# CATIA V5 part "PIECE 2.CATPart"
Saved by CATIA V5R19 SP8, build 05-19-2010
Part number: PIECE 2
Bounding box of the stored display mesh (mm): x -6 to 0, y -17.5 to 17.5, z -1 to 19
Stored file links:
  C:\Users\ThinkMotion\Desktop\EU_thinkMotion\iao\IAO_MMS_Groupe3\jbuffard\jbuffard\PIECE 2.CATPart
  C:\Users\ThinkMotion\Desktop\EU_thinkMotion\iao\IAO_MMS_Groupe3\jbuffard\jbuffard\Mecanisme a coulisse a quatre elements de la griffe d'une camera.CATProduct
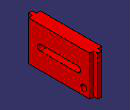
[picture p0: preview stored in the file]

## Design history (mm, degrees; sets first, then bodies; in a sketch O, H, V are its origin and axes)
External parameters (linked from other documents)
  `External.Diametre doigt/rainures` = 0.0015
  External.Largeur = 0.031
  `External.Demi-largeur` = 0.0155
Set1
  Plane1: linked copy from another document
  Plane2: linked copy from another document
  Point1 to Point3: linked copy from another document
  Plane3: linked copy from another document
Body1 (main body)
  Sketch1 on Plane1, origin (0, 0, 19), H (1, 0, 0), V (0, 1, 0)
    line L1 (-4, 17.5) -> (-2, 17.5)
    line L2 (-2, 17.5) -> (-2, 15.5)
    line L3 (-2, 15.5) -> (0, 15.5)
    line L4 (0, 15.5) -> (0, -15.5)
    line L5 (0, -15.5) -> (-2, -15.5)
    point P6 (-2, -15.5)
    line L6 (-2, -15.5) -> (-2, -17.5)
    line L7 (-2, -17.5) -> (-4, -17.5)
    line L8 (-4, -17.5) -> (-4, -15.5)
    point P9 (-4, -15.5)
    line L9 (-4, -15.5) -> (-6, -15.5)
    line L10 (-6, -15.5) -> (-6, 15.5)
    point P11 (-6, 15.5)
    line L11 (-6, 15.5) -> (-4, 15.5)
    point P12 (-4, 15.5)
    line L12 (-4, 15.5) -> (-4, 17.5)
    length L1 = 2
    length L3 = 2
    length L11 = 2
    length L6 = 2
    length L2 = 2
    length L4 = 31 {= External.Largeur}
    distance L3 H = 15.5 {= `External.Demi-largeur`}
    horizontal: L1 H, L3 H, L5 H, L7 H, L9 H, L11 H
    vertical: L2 V, L4 V, L6 V, L8 V, L10 V, L12 V
    coincidence: P6 L2, P9 L5, P11 L3, P12 L8, L4 V
  Pad1: profile Sketch1, direction (0, 0, -1), up to Plane2
  Sketch2 on yz-plane, origin (0, 0, 0), H (0, 1, 0), V (0, 0, 1)
    arc A1 centre (9.5, 9) radius 1.5 from (9.5, 7.5) to (9.5, 10.5) ccw
    point P1 (9.5, 9)
    arc A2 centre (-9.5, 9) radius 1.5 from (-9.5, 10.5) to (-9.5, 7.5) ccw
    point P2 (-9.5, 9)
    reference projected point E1 (9.5, 9) from Point1
    reference projected point E2 (-9.5, 9) from Point2
    line L1 (-9.5, 10.5) -> (9.5, 10.5)
    line L2 (-9.5, 7.5) -> (9.5, 7.5)
    circle A3 centre (12.5, 2.5) radius 1.5
    point P7 (12.5, 2.5)
    reference projected point E3 (12.5, 2.5) from Point3
    radius A1 = 1.5 {= `External.Diametre doigt/rainures`}
    radius A2 = 1.5 {= `External.Diametre doigt/rainures`}
    radius A3 = 1.5
    coincidence: P1 E1, P2 E2, E3 P7
    tangency: L1 A2, L1 A1, L2 A1
    parallelism: L2 L1
  Pocket1: profile Sketch2, direction (-1, 0, 0), up to Plane3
